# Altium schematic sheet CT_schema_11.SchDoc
size 146 x 119 mm
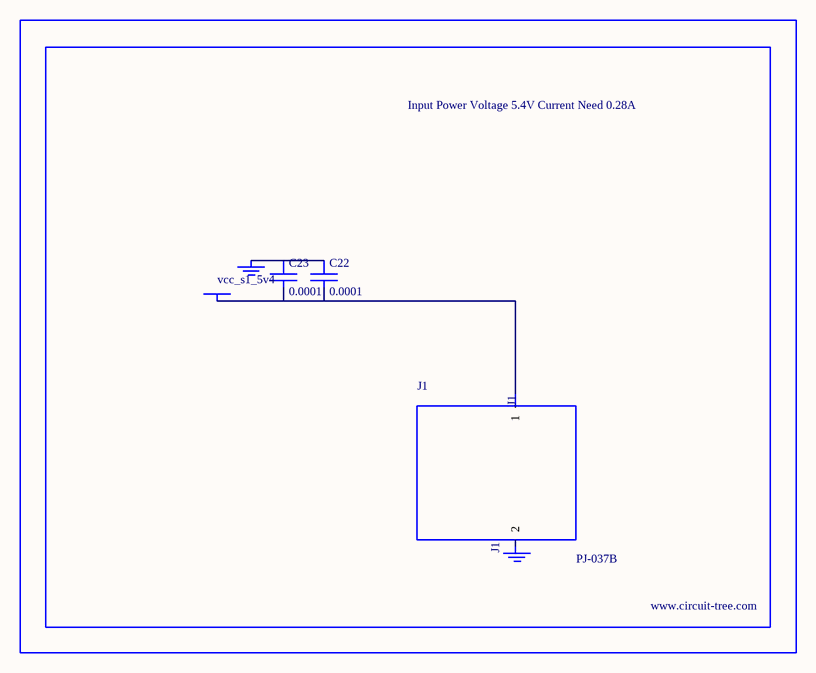
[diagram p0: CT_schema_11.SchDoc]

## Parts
BORDER10  (no value)
C22  0.0001  [EXV-9H]
C23  0.0001  [EXV-9H]
GND_INSTANCE_10_0  (no value)
GND_INSTANCE_10_1  (no value)
J1  PJ-037B  [PJ-037B_PACKAGE]
POWER_INSTANCE_10_0  vcc_s1_5v4

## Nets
NetC22_1: C22.1 C23.1 GND_INSTANCE_10_0.0(GND)
NetC22_2: C22.2 C23.2 J1.1 POWER_INSTANCE_10_0.0(PWR)

Not connected (* = marked no-connect by the designer): GND_INSTANCE_10_1 0(GND); J1 2

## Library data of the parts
BORDER10 = BORDER_PAGE10
C22 C23 = EDK107M035A9HAA
GND_INSTANCE_10_0 GND_INSTANCE_10_1 = GND
POWER_INSTANCE_10_0 = PWR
